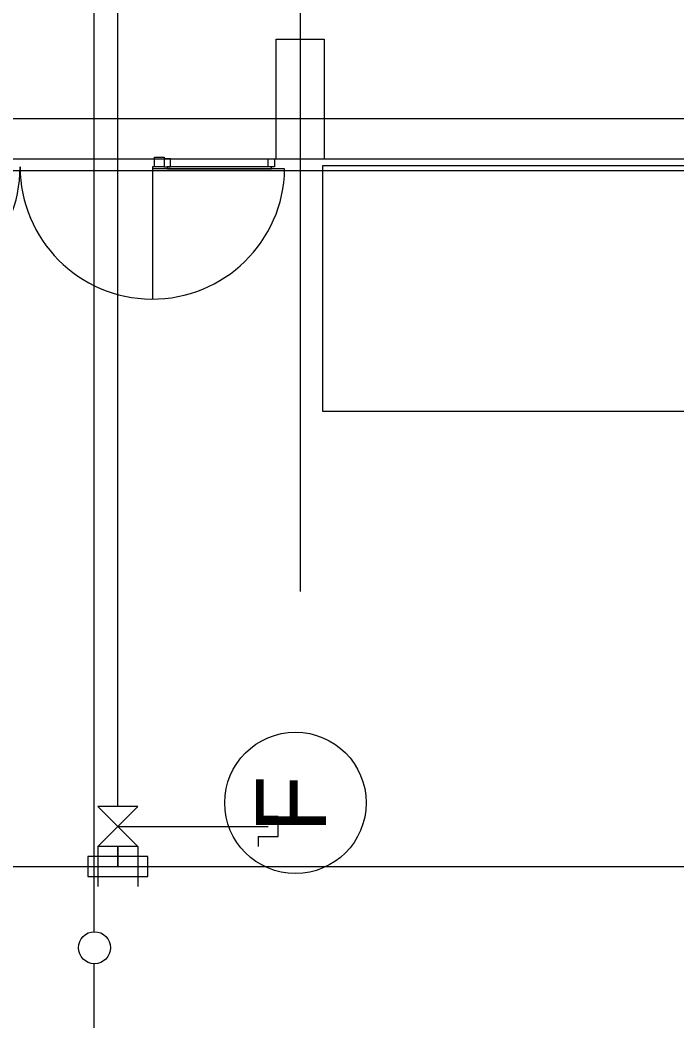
# Model space of a CAD drawing. Extents: x -264205 to -263659, y -1242401 to -1242060.
# Drawn here: x -263887.96 to -263879.77, y -1242252.15 to -1242239.58 of the extents above; entities that cross this region are included whole.
import ezdxf

# ---------------------------------------------------------------- set-up
doc = ezdxf.new("R2010")
doc.units = 0
for name, color, linetype in [('OBRUBNIKY_KOMUNIKACIE_PROJEKT', 7, 'Continuous'), ('OSI_STAVBY_KFA', 7, 'Continuous'), ('SITUACIA_DSP_2D', 7, 'Continuous')]:
    doc.layers.add(name, color=color, linetype=linetype)

msp = doc.modelspace()

# ---------------------------------------------------------------- linework, layer by layer
at = {"layer": 'OBRUBNIKY_KOMUNIKACIE_PROJEKT'}
msp.add_line((-263822.79, -1242241.457), (-263894.968, -1242241.457), dxfattribs=at)
at = {"layer": 'OSI_STAVBY_KFA'}
for p, q in [((-263884.468, -1242083.237), (-263884.468, -1242246.707)), ((-263792.653, -1242240.807), (-263911.523, -1242240.807))]:
    msp.add_line(p, q, dxfattribs=at)
msp.add_circle((-263884.528, -1242249.345), 0.882, dxfattribs=at)
at = {"layer": 'SITUACIA_DSP_2D'}
for p, q in [((-263887.043, -1242235.757), (-263887.043, -1242250.954)), ((-263886.743, -1242249.39), (-263886.743, -1242235.757)), ((-263884.768, -1242241.312), (-263884.768, -1242239.812)), ((-263884.768, -1242239.812), (-263884.168, -1242239.812)), ((-263884.168, -1242239.812), (-263884.168, -1242241.312)), ((-263894.581, -1242241.307), (-263822.79, -1242241.307)), ((-263886.288, -1242241.407), (-263886.288, -1242241.287)), ((-263886.288, -1242241.287), (-263886.168, -1242241.287)), ((-263886.168, -1242241.287), (-263886.168, -1242241.407)), ((-263886.088, -1242241.307), (-263886.168, -1242241.307)), ((-263886.168, -1242241.307), (-263886.168, -1242241.407)), ((-263886.088, -1242241.407), (-263886.088, -1242241.307)), ((-263884.868, -1242241.407), (-263884.868, -1242241.307)), ((-263884.868, -1242241.307), (-263884.788, -1242241.307)), ((-263884.788, -1242241.307), (-263884.788, -1242241.407)), ((-263884.168, -1242241.312), (-263884.768, -1242241.312)), ((-263884.188, -1242244.458), (-263884.188, -1242241.388)), ((-263884.188, -1242241.388), (-263876.738, -1242241.388)), ((-263822.79, -1242241.457), (-263894.968, -1242241.457)), ((-263886.288, -1242241.407), (-263886.313, -1242241.407)), ((-263886.313, -1242241.407), (-263886.313, -1242243.057)), ((-263884.663, -1242241.432), (-263886.313, -1242241.432)), ((-263886.168, -1242241.407), (-263886.288, -1242241.407)), ((-263886.168, -1242241.407), (-263886.128, -1242241.407)), ((-263884.828, -1242241.407), (-263886.128, -1242241.407)), ((-263886.128, -1242241.407), (-263886.128, -1242241.432)), ((-263886.128, -1242241.407), (-263886.088, -1242241.407)), ((-263886.128, -1242241.432), (-263884.828, -1242241.432)), ((-263884.828, -1242241.407), (-263884.868, -1242241.407)), ((-263884.828, -1242241.432), (-263884.828, -1242241.407)), ((-263884.788, -1242241.407), (-263884.828, -1242241.407)), ((-263876.738, -1242244.458), (-263884.188, -1242244.458)), ((-263886.493, -1242249.39), (-263886.993, -1242249.39)), ((-263886.993, -1242249.89), (-263886.493, -1242249.39)), ((-263886.993, -1242249.39), (-263886.493, -1242249.89)), ((-263884.993, -1242249.515), (-263884.993, -1242249.39)), ((-263884.743, -1242249.515), (-263884.993, -1242249.515)), ((-263884.743, -1242249.765), (-263884.743, -1242249.515)), ((-263886.743, -1242249.64), (-263884.868, -1242249.64)), ((-263884.993, -1242249.765), (-263884.993, -1242249.89)), ((-263884.993, -1242249.765), (-263884.743, -1242249.765)), ((-263886.493, -1242249.89), (-263886.993, -1242249.89)), ((-263886.993, -1242249.89), (-263886.993, -1242250.39)), ((-263886.743, -1242250.14), (-263886.743, -1242249.89)), ((-263886.743, -1242249.89), (-263886.743, -1242250.14)), ((-263886.493, -1242249.89), (-263886.493, -1242250.39)), ((-263886.368, -1242250.015), (-263887.118, -1242250.015)), ((-263887.118, -1242250.015), (-263887.118, -1242250.265)), ((-263886.368, -1242250.265), (-263886.368, -1242250.015)), ((-263924.143, -1242250.14), (-263822.79, -1242250.14)), ((-263887.118, -1242250.265), (-263886.368, -1242250.265)), ((-263887.043, -1242251.353), (-263887.043, -1242252.153))]:
    msp.add_line(p, q, dxfattribs=at)
msp.add_circle((-263887.036, -1242251.153), 0.2, dxfattribs=at)
for centre, start, end in [((-263889.613, -1242241.407), 180.8682, 0), ((-263886.313, -1242241.407), 180, 359.1318)]:
    msp.add_arc(centre, 1.65, start, end, dxfattribs=at)

# ---------------------------------------------------------------- texts
at = {"layer": 'OSI_STAVBY_KFA'}
msp.add_text('F', height=0.875, rotation=90, dxfattribs=at).set_placement((-263884.147, -1242249.718))

doc.saveas('drawing.dxf')
